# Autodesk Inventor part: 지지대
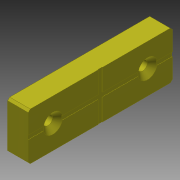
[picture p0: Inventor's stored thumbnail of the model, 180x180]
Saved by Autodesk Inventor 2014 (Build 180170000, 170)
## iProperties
Created: 2017-04
Part Number: 지지대
Material: 강철
Document SubType Name: Modeling
Designer: mduedu
Density: 7.85 g/cm^3
Mass: 97.8484 g
Surface Area: 48.4895 cm^2
Volume: 12.4648 cm^3
Appearance: 밝은 황색
Author: mduedu
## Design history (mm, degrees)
sketch "스케치1"
  geometry: L1 (23, -35)-(23, 35); L2 (0, -35)-(0, 35); L3 (0, 35)-(23, 35); L4 (0, -35)-(23, -35); 2 further points
  constraints: 8 end point, 2 parallel, 1 coincident, 1 midpoint, 1 perpendicular, 1 vertical
  dimensions: "d1" = 23 distance between parallel lines of L2 L1; "d15" = 70 distance of L1.start L1.end
extrude "돌출1" new body sketch "스케치1" distance "d2" = 8; taper "d3" = 0 deg
chamfer "모따기2" distance "d16" = 1; stored, may be unused: second distance "d17" = 2, angle "d18" = 45 deg
sketch "스케치2"
  geometry: L1 (1, -35)-(22, -35) reference; L2 (23, -34)-(23, 34) reference; L3 (22, 35)-(1, 35) reference; L4 (0, 34)-(0, -34) reference; L5 (11.5, 35)-(11.5, -35); L6 (23, 0)-(0, 0); L7 (1, -35)-(0, -34) reference; L8 (23, -34)-(22, -35) reference; L9 (22, 35)-(23, 34) reference; L10 (0, 34)-(1, 35) reference; 2 further points
  constraints: 4 end point, 4 midpoint, 1 point on line, 1 symmetric about line
  dimensions: "d7" = 12 distance from line of point (11.5, 23) L3
  node "투영된 루프1"
sketch "스케치3"
  geometry: 4 further points
  constraints: 2 coincident
hole "구멍1" sketch "스케치3" at (11.5, 23), (11.5, -23) diameter "d8" = 4.5; stored, may be unused: countersink angle "d12" = 90 deg, drill point angle "d14" = 0 deg; dims "d9" = 6, "d10" = 9.4, "d11" = 2, "d13" = 8
sketch "스케치4"
  geometry: L1 (-35, 22)-(-35, 1) reference; L2 (35, 1)-(35, 22) reference; L3 (34, 23)-(-34, 23) reference; L4 (-34, 0)-(34, 0) reference; L5 (-35, 11.5)-(35, 11.5); L6 (0, 23)-(0, 0); L7 (-35, 12.5)-(35, 12.5); L8 (-35, 10.5)-(35, 10.5); L9 (-1, 23)-(-1, 0); L10 (1, 23)-(1, 0)
  constraints: 12 end point, 8 point on line, 4 parallel, 3 midpoint, 3 perpendicular
  dimensions: "d19" = 1 distance between parallel lines of L7 L5; "d21" = 1 distance between parallel lines of L8 L5; "d22" = 1 distance between parallel lines of L9 L6; "d23" = 1 distance between parallel lines of L10 L6
extrude "돌출2" cut sketch "스케치4" distance "d24" = 0.2; taper "d25" = 0 deg
extrude "돌출3" cut sketch "스케치4" distance "d26" = 0.2; taper "d27" = 0 deg
fillet "모깎기1" dims "d28" = 0.2
node "솔리드2"
node "솔리드1"
